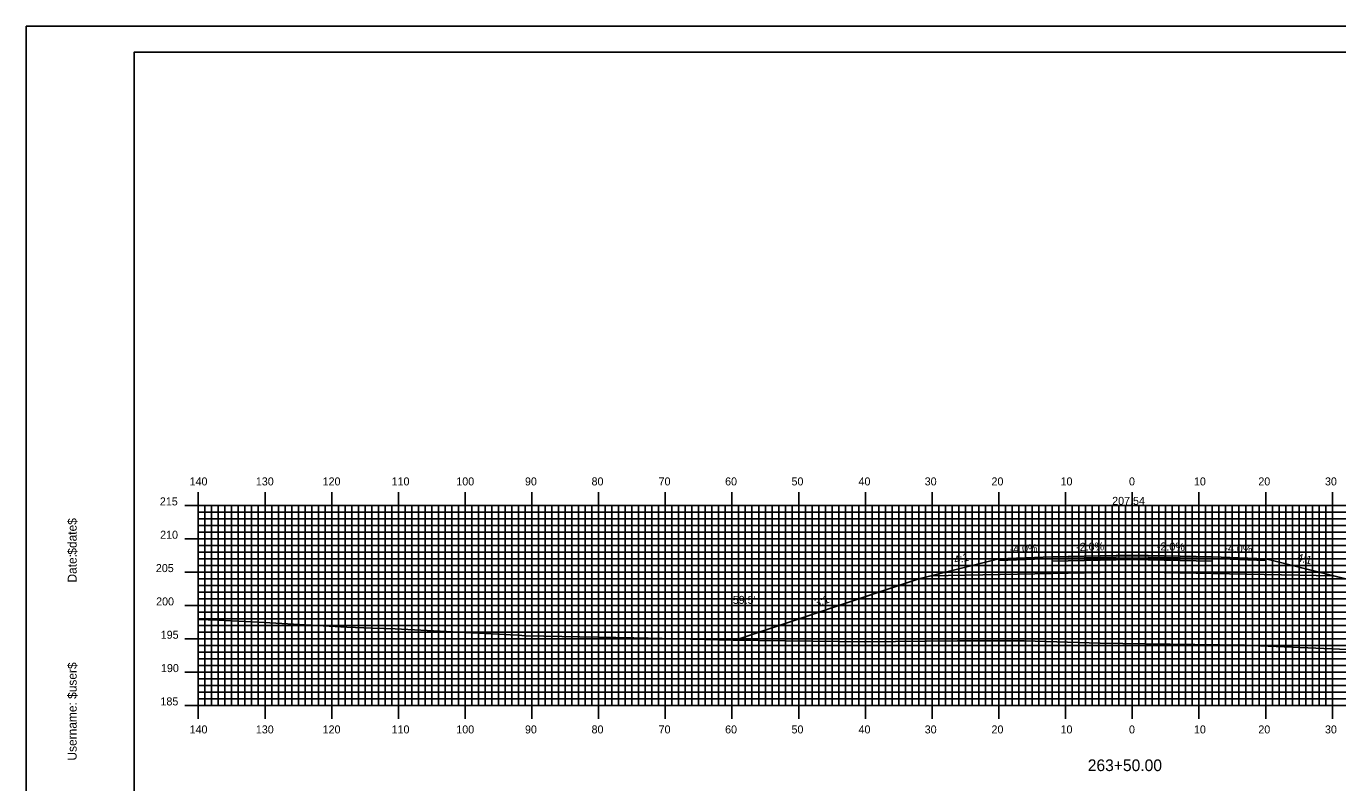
# Model space of a CAD drawing. Extents: x 1806651 to 1806995, y 442591 to 442811.
# Drawn here: x 1806651.5 to 1806848.1, y 442697.1 to 442810.5 of the extents above; entities that cross this region are included whole.
import ezdxf

# ---------------------------------------------------------------- set-up
doc = ezdxf.new("R2010")
doc.units = 0
for name, color, linetype in [('ANNOTATION', 7, 'Continuous'), ('BORDER', 7, 'Continuous'), ('D_Roadway_Centerline', 7, 'Continuous'), ('D_Roadway_Centerline_Text', 7, 'Continuous'), ('D_Roadway_Edge_Shoulder', 7, 'Continuous'), ('D_Roadway_Edge_TW', 7, 'Continuous'), ('D_Roadway_Pavement', 7, 'Continuous'), ('D_Roadway_SlopeLines', 7, 'Continuous'), ('D_Roadway_SubGrade', 7, 'Continuous'), ('D_Text_Standard', 7, 'Continuous'), ('H_V ANNOTATION', 7, 'Continuous'), ('MAJOR', 7, 'Continuous'), ('MINOR', 7, 'Continuous'), ('PLOT BOUNDARY', 7, 'Continuous'), ('S_Roadway_Centerline', 7, 'Continuous')]:
    doc.layers.add(name, color=color, linetype=linetype)

msp = doc.modelspace()

# ---------------------------------------------------------------- linework, layer by layer
at = {"layer": 'BORDER'}
msp.add_lwpolyline([(1806667.65, 442596.67), (1806987.65, 442596.67), (1806987.65, 442806.67), (1806667.65, 442806.67)], close=True, dxfattribs=at)
at = {"layer": 'D_Roadway_Centerline'}
msp.add_lwpolyline([(1806757.75, 442718.48), (1806785.25, 442727.65), (1806787.07, 442728.1), (1806797.25, 442730.65), (1806805.25, 442730.97), (1806817.25, 442731.21), (1806829.25, 442730.97), (1806837.25, 442730.65), (1806847.42, 442728.1), (1806849.25, 442727.65), (1806881.77, 442716.8)], dxfattribs=at)
at = {"layer": 'D_Roadway_Edge_Shoulder'}
for points in [[(1806805.25, 442730.97), (1806797.25, 442730.65), (1806797.25, 442730.4), (1806805.25, 442730.72)], [(1806829.25, 442730.97), (1806837.25, 442730.65), (1806837.25, 442730.4), (1806829.25, 442730.72)]]:
    msp.add_lwpolyline(points, close=True, dxfattribs=at)
at = {"layer": 'D_Roadway_Edge_TW'}
msp.add_lwpolyline([(1806805.25, 442730.72), (1806805.25, 442730.97), (1806817.25, 442731.21), (1806829.25, 442730.97), (1806829.25, 442730.72), (1806817.25, 442730.96)], close=True, dxfattribs=at)
at = {"layer": 'D_Roadway_Pavement'}
msp.add_lwpolyline([(1806805.25, 442730.3), (1806805.25, 442730.72), (1806817.25, 442730.96), (1806829.25, 442730.72), (1806829.25, 442730.3), (1806817.25, 442730.54)], close=True, dxfattribs=at)
at = {"layer": 'D_Roadway_SlopeLines'}
for points in [[(1806797.25, 442730.65), (1806785.25, 442727.65), (1806757.75, 442718.48)], [(1806837.25, 442730.65), (1806849.25, 442727.65), (1806881.77, 442716.8)]]:
    msp.add_lwpolyline(points, dxfattribs=at)
at = {"layer": 'D_Roadway_SubGrade'}
msp.add_lwpolyline([(1806805.25, 442728.47), (1806787.07, 442728.1), (1806797.25, 442730.65), (1806797.25, 442730.4), (1806805.25, 442730.72), (1806817.25, 442730.96), (1806829.25, 442730.72), (1806837.25, 442730.4), (1806837.25, 442730.65), (1806847.42, 442728.1), (1806829.25, 442728.47), (1806817.25, 442728.71)], close=True, dxfattribs=at)
at = {"layer": 'MAJOR'}
for p, q in [((1806677.25, 442740.67), (1806677.25, 442738.67)), ((1806687.25, 442740.67), (1806687.25, 442738.67)), ((1806697.25, 442740.67), (1806697.25, 442738.67)), ((1806707.25, 442740.67), (1806707.25, 442738.67)), ((1806717.25, 442740.67), (1806717.25, 442738.67)), ((1806727.25, 442740.67), (1806727.25, 442738.67)), ((1806737.25, 442740.67), (1806737.25, 442738.67)), ((1806747.25, 442740.67), (1806747.25, 442738.67)), ((1806757.25, 442740.67), (1806757.25, 442738.67)), ((1806767.25, 442740.67), (1806767.25, 442738.67)), ((1806777.25, 442740.67), (1806777.25, 442738.67)), ((1806787.25, 442740.67), (1806787.25, 442738.67)), ((1806797.25, 442740.67), (1806797.25, 442738.67)), ((1806807.25, 442740.67), (1806807.25, 442738.67)), ((1806817.25, 442740.67), (1806817.25, 442738.67)), ((1806827.25, 442740.67), (1806827.25, 442738.67)), ((1806837.25, 442740.67), (1806837.25, 442738.67)), ((1806847.25, 442740.67), (1806847.25, 442738.67)), ((1806675.24, 442738.67), (1806677.25, 442738.67)), ((1806677.25, 442738.67), (1806957.25, 442738.67)), ((1806677.25, 442708.67), (1806677.25, 442738.67)), ((1806677.25, 442708.67), (1806677.25, 442738.67)), ((1806677.25, 442738.67), (1806957.25, 442738.67)), ((1806687.25, 442708.67), (1806687.25, 442738.67)), ((1806697.25, 442708.67), (1806697.25, 442738.67)), ((1806707.25, 442708.67), (1806707.25, 442738.67)), ((1806717.25, 442708.67), (1806717.25, 442738.67)), ((1806727.25, 442708.67), (1806727.25, 442738.67)), ((1806737.25, 442708.67), (1806737.25, 442738.67)), ((1806747.25, 442708.67), (1806747.25, 442738.67)), ((1806757.25, 442708.67), (1806757.25, 442738.67)), ((1806767.25, 442708.67), (1806767.25, 442738.67)), ((1806777.25, 442708.67), (1806777.25, 442738.67)), ((1806787.25, 442708.67), (1806787.25, 442738.67)), ((1806797.25, 442708.67), (1806797.25, 442738.67)), ((1806807.25, 442708.67), (1806807.25, 442738.67)), ((1806817.25, 442708.67), (1806817.25, 442738.67)), ((1806827.25, 442708.67), (1806827.25, 442738.67)), ((1806837.25, 442708.67), (1806837.25, 442738.67)), ((1806847.25, 442708.67), (1806847.25, 442738.67)), ((1806675.24, 442733.67), (1806677.25, 442733.67)), ((1806677.25, 442733.67), (1806957.25, 442733.67)), ((1806675.24, 442728.67), (1806677.25, 442728.67)), ((1806677.25, 442728.67), (1806957.25, 442728.67)), ((1806675.24, 442723.67), (1806677.25, 442723.67)), ((1806677.25, 442723.67), (1806957.25, 442723.67)), ((1806675.24, 442718.67), (1806677.25, 442718.67)), ((1806677.25, 442718.67), (1806957.25, 442718.67)), ((1806675.24, 442713.67), (1806677.25, 442713.67)), ((1806677.25, 442713.67), (1806957.25, 442713.67)), ((1806675.24, 442708.67), (1806677.25, 442708.67)), ((1806677.25, 442708.67), (1806957.25, 442708.67)), ((1806677.25, 442708.67), (1806957.25, 442708.67)), ((1806677.25, 442706.66), (1806677.25, 442708.67)), ((1806687.25, 442706.66), (1806687.25, 442708.67)), ((1806697.25, 442706.66), (1806697.25, 442708.67)), ((1806707.25, 442706.66), (1806707.25, 442708.67)), ((1806717.25, 442706.66), (1806717.25, 442708.67)), ((1806727.25, 442706.66), (1806727.25, 442708.67)), ((1806737.25, 442706.66), (1806737.25, 442708.67)), ((1806747.25, 442706.66), (1806747.25, 442708.67)), ((1806757.25, 442706.66), (1806757.25, 442708.67)), ((1806767.25, 442706.66), (1806767.25, 442708.67)), ((1806777.25, 442706.66), (1806777.25, 442708.67)), ((1806787.25, 442706.66), (1806787.25, 442708.67)), ((1806797.25, 442706.66), (1806797.25, 442708.67)), ((1806807.25, 442706.66), (1806807.25, 442708.67)), ((1806817.25, 442706.66), (1806817.25, 442708.67)), ((1806827.25, 442706.66), (1806827.25, 442708.67)), ((1806837.25, 442706.66), (1806837.25, 442708.67)), ((1806847.25, 442706.66), (1806847.25, 442708.67))]:
    msp.add_line(p, q, dxfattribs=at)
at = {"layer": 'MINOR'}
for p, q in [((1806677.25, 442737.67), (1806957.25, 442737.67)), ((1806677.25, 442737.67), (1806679.25, 442737.67)), ((1806678.25, 442708.67), (1806678.25, 442738.67)), ((1806679.25, 442708.67), (1806679.25, 442738.67)), ((1806680.25, 442708.67), (1806680.25, 442738.67)), ((1806681.25, 442708.67), (1806681.25, 442738.67)), ((1806682.25, 442708.67), (1806682.25, 442738.67)), ((1806683.25, 442708.67), (1806683.25, 442738.67)), ((1806684.25, 442708.67), (1806684.25, 442738.67)), ((1806685.25, 442708.67), (1806685.25, 442738.67)), ((1806686.25, 442708.67), (1806686.25, 442738.67)), ((1806688.25, 442708.67), (1806688.25, 442738.67)), ((1806689.25, 442708.67), (1806689.25, 442738.67)), ((1806690.25, 442708.67), (1806690.25, 442738.67)), ((1806691.25, 442708.67), (1806691.25, 442738.67)), ((1806692.25, 442708.67), (1806692.25, 442738.67)), ((1806693.25, 442708.67), (1806693.25, 442738.67)), ((1806694.25, 442708.67), (1806694.25, 442738.67)), ((1806695.25, 442708.67), (1806695.25, 442738.67)), ((1806696.25, 442708.67), (1806696.25, 442738.67)), ((1806698.25, 442708.67), (1806698.25, 442738.67)), ((1806699.25, 442708.67), (1806699.25, 442738.67)), ((1806700.25, 442708.67), (1806700.25, 442738.67)), ((1806701.25, 442708.67), (1806701.25, 442738.67)), ((1806702.25, 442708.67), (1806702.25, 442738.67)), ((1806703.25, 442708.67), (1806703.25, 442738.67)), ((1806704.25, 442708.67), (1806704.25, 442738.67)), ((1806705.25, 442708.67), (1806705.25, 442738.67)), ((1806706.25, 442708.67), (1806706.25, 442738.67)), ((1806708.25, 442708.67), (1806708.25, 442738.67)), ((1806709.25, 442708.67), (1806709.25, 442738.67)), ((1806710.25, 442708.67), (1806710.25, 442738.67)), ((1806711.25, 442708.67), (1806711.25, 442738.67)), ((1806712.25, 442708.67), (1806712.25, 442738.67)), ((1806713.25, 442708.67), (1806713.25, 442738.67)), ((1806714.25, 442708.67), (1806714.25, 442738.67)), ((1806715.25, 442708.67), (1806715.25, 442738.67)), ((1806716.25, 442708.67), (1806716.25, 442738.67)), ((1806718.25, 442708.67), (1806718.25, 442738.67)), ((1806719.25, 442708.67), (1806719.25, 442738.67)), ((1806720.25, 442708.67), (1806720.25, 442738.67)), ((1806721.25, 442708.67), (1806721.25, 442738.67)), ((1806722.25, 442708.67), (1806722.25, 442738.67)), ((1806723.25, 442708.67), (1806723.25, 442738.67)), ((1806724.25, 442708.67), (1806724.25, 442738.67)), ((1806725.25, 442708.67), (1806725.25, 442738.67)), ((1806726.25, 442708.67), (1806726.25, 442738.67)), ((1806728.25, 442708.67), (1806728.25, 442738.67)), ((1806729.25, 442708.67), (1806729.25, 442738.67)), ((1806730.25, 442708.67), (1806730.25, 442738.67)), ((1806731.25, 442708.67), (1806731.25, 442738.67)), ((1806732.25, 442708.67), (1806732.25, 442738.67)), ((1806733.25, 442708.67), (1806733.25, 442738.67)), ((1806734.25, 442708.67), (1806734.25, 442738.67)), ((1806735.25, 442708.67), (1806735.25, 442738.67)), ((1806736.25, 442708.67), (1806736.25, 442738.67)), ((1806738.25, 442708.67), (1806738.25, 442738.67)), ((1806739.25, 442708.67), (1806739.25, 442738.67)), ((1806740.25, 442708.67), (1806740.25, 442738.67)), ((1806741.25, 442708.67), (1806741.25, 442738.67)), ((1806742.25, 442708.67), (1806742.25, 442738.67)), ((1806743.25, 442708.67), (1806743.25, 442738.67)), ((1806744.25, 442708.67), (1806744.25, 442738.67)), ((1806745.25, 442708.67), (1806745.25, 442738.67)), ((1806746.25, 442708.67), (1806746.25, 442738.67)), ((1806748.25, 442708.67), (1806748.25, 442738.67)), ((1806749.25, 442708.67), (1806749.25, 442738.67)), ((1806750.25, 442708.67), (1806750.25, 442738.67)), ((1806751.25, 442708.67), (1806751.25, 442738.67)), ((1806752.25, 442708.67), (1806752.25, 442738.67)), ((1806753.25, 442708.67), (1806753.25, 442738.67)), ((1806754.25, 442708.67), (1806754.25, 442738.67)), ((1806755.25, 442708.67), (1806755.25, 442738.67)), ((1806756.25, 442708.67), (1806756.25, 442738.67)), ((1806758.25, 442708.67), (1806758.25, 442738.67)), ((1806759.25, 442708.67), (1806759.25, 442738.67)), ((1806760.25, 442708.67), (1806760.25, 442738.67)), ((1806761.25, 442708.67), (1806761.25, 442738.67)), ((1806762.25, 442708.67), (1806762.25, 442738.67)), ((1806763.25, 442708.67), (1806763.25, 442738.67)), ((1806764.25, 442708.67), (1806764.25, 442738.67)), ((1806765.25, 442708.67), (1806765.25, 442738.67)), ((1806766.25, 442708.67), (1806766.25, 442738.67)), ((1806768.25, 442708.67), (1806768.25, 442738.67)), ((1806769.25, 442708.67), (1806769.25, 442738.67)), ((1806770.25, 442708.67), (1806770.25, 442738.67)), ((1806771.25, 442708.67), (1806771.25, 442738.67)), ((1806772.25, 442708.67), (1806772.25, 442738.67)), ((1806773.25, 442708.67), (1806773.25, 442738.67)), ((1806774.25, 442708.67), (1806774.25, 442738.67)), ((1806775.25, 442708.67), (1806775.25, 442738.67)), ((1806776.25, 442708.67), (1806776.25, 442738.67)), ((1806778.25, 442708.67), (1806778.25, 442738.67)), ((1806779.25, 442708.67), (1806779.25, 442738.67)), ((1806780.25, 442708.67), (1806780.25, 442738.67)), ((1806781.25, 442708.67), (1806781.25, 442738.67)), ((1806782.25, 442708.67), (1806782.25, 442738.67)), ((1806783.25, 442708.67), (1806783.25, 442738.67)), ((1806784.25, 442708.67), (1806784.25, 442738.67)), ((1806785.25, 442708.67), (1806785.25, 442738.67)), ((1806786.25, 442708.67), (1806786.25, 442738.67)), ((1806788.25, 442708.67), (1806788.25, 442738.67)), ((1806789.25, 442708.67), (1806789.25, 442738.67)), ((1806790.25, 442708.67), (1806790.25, 442738.67)), ((1806791.25, 442708.67), (1806791.25, 442738.67)), ((1806792.25, 442708.67), (1806792.25, 442738.67)), ((1806793.25, 442708.67), (1806793.25, 442738.67)), ((1806794.25, 442708.67), (1806794.25, 442738.67)), ((1806795.25, 442708.67), (1806795.25, 442738.67)), ((1806796.25, 442708.67), (1806796.25, 442738.67)), ((1806798.25, 442708.67), (1806798.25, 442738.67)), ((1806799.25, 442708.67), (1806799.25, 442738.67)), ((1806800.25, 442708.67), (1806800.25, 442738.67)), ((1806801.25, 442708.67), (1806801.25, 442738.67)), ((1806802.25, 442708.67), (1806802.25, 442738.67)), ((1806803.25, 442708.67), (1806803.25, 442738.67)), ((1806804.25, 442708.67), (1806804.25, 442738.67)), ((1806805.25, 442708.67), (1806805.25, 442738.67)), ((1806806.25, 442708.67), (1806806.25, 442738.67)), ((1806808.25, 442708.67), (1806808.25, 442738.67)), ((1806809.25, 442708.67), (1806809.25, 442738.67)), ((1806810.25, 442708.67), (1806810.25, 442738.67)), ((1806811.25, 442708.67), (1806811.25, 442738.67)), ((1806812.25, 442708.67), (1806812.25, 442738.67)), ((1806813.25, 442708.67), (1806813.25, 442738.67)), ((1806814.25, 442708.67), (1806814.25, 442738.67)), ((1806815.25, 442708.67), (1806815.25, 442738.67)), ((1806816.25, 442708.67), (1806816.25, 442738.67)), ((1806818.25, 442708.67), (1806818.25, 442738.67)), ((1806819.25, 442708.67), (1806819.25, 442738.67)), ((1806820.25, 442708.67), (1806820.25, 442738.67)), ((1806821.25, 442708.67), (1806821.25, 442738.67)), ((1806822.25, 442708.67), (1806822.25, 442738.67)), ((1806823.25, 442708.67), (1806823.25, 442738.67)), ((1806824.25, 442708.67), (1806824.25, 442738.67)), ((1806825.25, 442708.67), (1806825.25, 442738.67)), ((1806826.25, 442708.67), (1806826.25, 442738.67)), ((1806828.25, 442708.67), (1806828.25, 442738.67)), ((1806829.25, 442708.67), (1806829.25, 442738.67)), ((1806830.25, 442708.67), (1806830.25, 442738.67)), ((1806831.25, 442708.67), (1806831.25, 442738.67)), ((1806832.25, 442708.67), (1806832.25, 442738.67)), ((1806833.25, 442708.67), (1806833.25, 442738.67)), ((1806834.25, 442708.67), (1806834.25, 442738.67)), ((1806835.25, 442708.67), (1806835.25, 442738.67)), ((1806836.25, 442708.67), (1806836.25, 442738.67)), ((1806838.25, 442708.67), (1806838.25, 442738.67)), ((1806839.25, 442708.67), (1806839.25, 442738.67)), ((1806840.25, 442708.67), (1806840.25, 442738.67)), ((1806841.25, 442708.67), (1806841.25, 442738.67)), ((1806842.25, 442708.67), (1806842.25, 442738.67)), ((1806843.25, 442708.67), (1806843.25, 442738.67)), ((1806844.25, 442708.67), (1806844.25, 442738.67)), ((1806845.25, 442708.67), (1806845.25, 442738.67)), ((1806846.25, 442708.67), (1806846.25, 442738.67)), ((1806677.25, 442736.67), (1806957.25, 442736.67)), ((1806677.25, 442736.67), (1806679.25, 442736.67)), ((1806677.25, 442735.67), (1806957.25, 442735.67)), ((1806677.25, 442735.67), (1806679.25, 442735.67)), ((1806677.25, 442734.67), (1806957.25, 442734.67)), ((1806677.25, 442734.67), (1806679.25, 442734.67)), ((1806677.25, 442732.67), (1806957.25, 442732.67)), ((1806677.25, 442732.67), (1806679.25, 442732.67)), ((1806677.25, 442731.67), (1806957.25, 442731.67)), ((1806677.25, 442731.67), (1806679.25, 442731.67)), ((1806677.25, 442730.67), (1806957.25, 442730.67)), ((1806677.25, 442730.67), (1806679.25, 442730.67)), ((1806677.25, 442729.67), (1806957.25, 442729.67)), ((1806677.25, 442729.67), (1806679.25, 442729.67)), ((1806677.25, 442727.67), (1806957.25, 442727.67)), ((1806677.25, 442727.67), (1806679.25, 442727.67)), ((1806677.25, 442726.67), (1806957.25, 442726.67)), ((1806677.25, 442726.67), (1806679.25, 442726.67)), ((1806677.25, 442725.67), (1806957.25, 442725.67)), ((1806677.25, 442725.67), (1806679.25, 442725.67)), ((1806677.25, 442724.67), (1806957.25, 442724.67)), ((1806677.25, 442724.67), (1806679.25, 442724.67)), ((1806677.25, 442722.67), (1806957.25, 442722.67)), ((1806677.25, 442722.67), (1806679.25, 442722.67)), ((1806677.25, 442721.67), (1806957.25, 442721.67)), ((1806677.25, 442721.67), (1806679.25, 442721.67)), ((1806677.25, 442720.67), (1806957.25, 442720.67)), ((1806677.25, 442720.67), (1806679.25, 442720.67)), ((1806677.25, 442719.67), (1806957.25, 442719.67)), ((1806677.25, 442719.67), (1806679.25, 442719.67)), ((1806677.25, 442717.67), (1806957.25, 442717.67)), ((1806677.25, 442717.67), (1806679.25, 442717.67)), ((1806677.25, 442716.67), (1806957.25, 442716.67)), ((1806677.25, 442716.67), (1806679.25, 442716.67)), ((1806677.25, 442715.67), (1806957.25, 442715.67)), ((1806677.25, 442715.67), (1806679.25, 442715.67)), ((1806677.25, 442714.67), (1806957.25, 442714.67)), ((1806677.25, 442714.67), (1806679.25, 442714.67)), ((1806677.25, 442712.67), (1806957.25, 442712.67)), ((1806677.25, 442712.67), (1806679.25, 442712.67)), ((1806677.25, 442711.67), (1806957.25, 442711.67)), ((1806677.25, 442711.67), (1806679.25, 442711.67)), ((1806677.25, 442710.67), (1806957.25, 442710.67)), ((1806677.25, 442710.67), (1806679.25, 442710.67)), ((1806677.25, 442709.67), (1806957.25, 442709.67)), ((1806677.25, 442709.67), (1806679.25, 442709.67))]:
    msp.add_line(p, q, dxfattribs=at)
at = {"layer": 'PLOT BOUNDARY'}
msp.add_lwpolyline([(1806651.46, 442590.55), (1806991.46, 442590.55), (1806991.46, 442810.55), (1806651.46, 442810.55)], close=True, dxfattribs=at)
at = {"layer": 'S_Roadway_Centerline'}
msp.add_lwpolyline([(1806677.25, 442721.56), (1806680.22, 442721.47), (1806685.34, 442721.2), (1806699.5, 442720.4), (1806703.38, 442720.27), (1806706.78, 442720.14), (1806724.06, 442719.25), (1806725.17, 442719.21), (1806726.35, 442719.13), (1806742.52, 442718.81), (1806757.44, 442718.48), (1806777.09, 442718.23), (1806791.05, 442718.38), (1806801.07, 442718.35), (1806812.42, 442718.03), (1806819.24, 442717.92), (1806834.08, 442717.73), (1806855.48, 442716.81)], dxfattribs=at)

# ---------------------------------------------------------------- texts
at = {"layer": 'ANNOTATION'}
for s, rotation, p in [('4:1', 14.0362, (1806790.69, 442729.87)), ('-4.0%', 2.2906, (1806798.88, 442731.51)), ('-2.0%', 1.1458, (1806808.85, 442731.84)), ('-2.0%', 358.8542, (1806820.93, 442731.93)), ('-4.0%', 357.7094, (1806831.04, 442731.7)), ('4:1', 345.9638, (1806841.84, 442730.36)), ('3:1', 18.4348, (1806769.84, 442723.42))]:
    msp.add_text(s, height=1.2, rotation=rotation, dxfattribs=at).set_placement(p)
at = {"layer": 'BORDER'}
for s, p in [('$date$', (1806659.02, 442731.28)), ('Date:', (1806659.02, 442727.1)), ('$user$', (1806659.02, 442709.65)), ('Username:', (1806659.02, 442700.4))]:
    msp.add_text(s, height=1.339, rotation=90, dxfattribs=at).set_placement(p)
at = {"layer": 'D_Roadway_Centerline'}
for s, p in [('C', (1806817.24, 442731.21)), ('L', (1806817.25, 442731.2))]:
    msp.add_text(s, height=0.0146, dxfattribs=at).set_placement(p)
at = {"layer": 'D_Roadway_Centerline_Text'}
msp.add_text('207.54', height=1.2, dxfattribs=at).set_placement((1806814.24, 442738.75))
at = {"layer": 'D_Text_Standard'}
msp.add_text("59.5'", height=1.2, dxfattribs=at).set_placement((1806757.37, 442723.9))
at = {"layer": 'H_V ANNOTATION'}
for s, height, p in [('140', 1.2, (1806675.95, 442741.67)), ('130', 1.2, (1806685.88, 442741.67)), ('120', 1.2, (1806695.89, 442741.67)), ('110', 1.2, (1806706.23, 442741.67)), ('100', 1.2, (1806715.93, 442741.67)), ('90', 1.2, (1806726.22, 442741.67)), ('80', 1.2, (1806736.2, 442741.67)), ('70', 1.2, (1806746.25, 442741.67)), ('60', 1.2, (1806756.22, 442741.67)), ('50', 1.2, (1806766.17, 442741.67)), ('40', 1.2, (1806776.22, 442741.67)), ('30', 1.2, (1806786.14, 442741.67)), ('20', 1.2, (1806796.15, 442741.67)), ('10', 1.2, (1806806.5, 442741.67)), ('0', 1.2, (1806816.76, 442741.67)), ('10', 1.2, (1806826.5, 442741.67)), ('20', 1.2, (1806836.15, 442741.67)), ('30', 1.2, (1806846.14, 442741.67)), ('215', 1.2, (1806671.49, 442738.67)), ('210', 1.2, (1806671.53, 442733.67)), ('205', 1.2, (1806670.89, 442728.67)), ('200', 1.2, (1806670.93, 442723.67)), ('195', 1.2, (1806671.62, 442718.67)), ('190', 1.2, (1806671.66, 442713.67)), ('185', 1.2, (1806671.58, 442708.67)), ('140', 1.2, (1806675.95, 442704.47)), ('130', 1.2, (1806685.88, 442704.47)), ('120', 1.2, (1806695.89, 442704.47)), ('110', 1.2, (1806706.23, 442704.47)), ('100', 1.2, (1806715.93, 442704.47)), ('90', 1.2, (1806726.22, 442704.47)), ('80', 1.2, (1806736.2, 442704.47)), ('70', 1.2, (1806746.25, 442704.47)), ('60', 1.2, (1806756.22, 442704.47)), ('50', 1.2, (1806766.17, 442704.47)), ('40', 1.2, (1806776.22, 442704.47)), ('30', 1.2, (1806786.14, 442704.47)), ('20', 1.2, (1806796.15, 442704.47)), ('10', 1.2, (1806806.5, 442704.47)), ('0', 1.2, (1806816.76, 442704.47)), ('10', 1.2, (1806826.5, 442704.47)), ('20', 1.2, (1806836.15, 442704.47)), ('30', 1.2, (1806846.14, 442704.47)), ('263+50.00', 1.75, (1806810.58, 442698.82))]:
    msp.add_text(s, height=height, dxfattribs=at).set_placement(p)
at = {"layer": 'MAJOR'}
msp.add_text('-', height=0.012, dxfattribs=at).set_placement((1806677.24, 442708.67))

doc.saveas('drawing.dxf')
